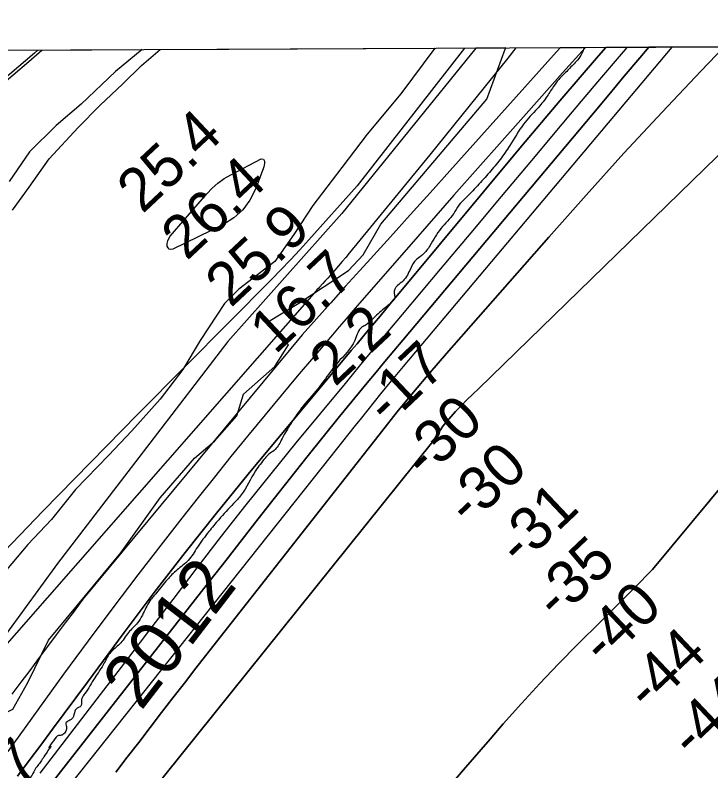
# Model space of a CAD drawing. Extents: x 3424494 to 3462436, y 522220 to 547718.
# Drawn here: x 3448142 to 3449221, y 544764 to 545936 of the extents above; entities that cross this region are included whole.
import ezdxf

# ---------------------------------------------------------------- set-up
doc = ezdxf.new("R2010")
doc.units = 0
for name, color, linetype in [('V-GRID-FRAM', 7, 'Continuous'), ('V-LEVE-TOET', 7, 'Continuous'), ('V-RIVR-EDGE', 7, 'Continuous'), ('V-RIVR-IDEN', 7, 'Continuous'), ('V-RIVR-RANG', 7, 'Continuous'), ('V-SITE-VEGE', 7, 'Continuous'), ('V-TOPO-DPTH', 7, 'Continuous'), ('V-TOPO-MAJR', 7, 'Continuous'), ('V-TOPO-MINR', 7, 'Continuous'), ('V-TOPO-WATR', 7, 'Continuous'), ('V-WETL-SWMP', 7, 'Continuous')]:
    doc.layers.add(name, color=color, linetype=linetype)

msp = doc.modelspace()

# ---------------------------------------------------------------- linework, layer by layer
at = {"layer": 'V-GRID-FRAM'}
for points in [[(3428547.8, 545793.2), (3460200.7, 545935.9)], [(3428547.8, 545793.2), (3451467.1, 545896.5)]]:
    msp.add_lwpolyline(points, dxfattribs=at)
at = {"layer": 'V-LEVE-TOET'}
msp.add_lwpolyline([(3448177, 545881.7), (3448171.9, 545876.8), (3448060.2, 545782.3), (3448035.6, 545758.1), (3448021.3, 545739), (3448005.8, 545710.4), (3447991.9, 545685.8), (3447953.7, 545644.5), (3447873.8, 545571), (3447770.9, 545482), (3447709.3, 545429.6), (3447592.4, 545332.3), (3447519.7, 545267.2), (3447440.2, 545198.9), (3447431.5, 545190.1), (3447416.4, 545175.4), (3447410.4, 545170.3), (3447402.1, 545163.9), (3447381.8, 545146.8), (3447242.3, 545026.9), (3447093.7, 544898.2), (3446965.7, 544788.2), (3446817.5, 544663.1)], dxfattribs=at)
at = {"layer": 'V-RIVR-EDGE'}
msp.add_spline([(3449024.5, 545885.5), (3449019.3, 545873.5), (3449011.8, 545864), (3448999, 545850.5), (3448985, 545836.1), (3448976.3, 545824.5), (3448965.5, 545808.1), (3448951.4, 545790.8), (3448930.4, 545766.9), (3448908.8, 545733.6), (3448893.9, 545712.1), (3448877.4, 545692), (3448858.8, 545671.4), (3448838.9, 545650.8), (3448829.8, 545641), (3448822, 545628.2), (3448802.1, 545605.2), (3448785.1, 545578.4), (3448774, 545564.8), (3448769, 545560.7), (3448761.1, 545553.7), (3448753.7, 545540.1), (3448748.7, 545530.6), (3448741.3, 545522), (3448732.6, 545514.6), (3448730.5, 545510.9), (3448729.7, 545504.3), (3448730.5, 545498.5), (3448726.4, 545491.9), (3448714, 545480.8), (3448695.8, 545464.4), (3448686.3, 545455.7), (3448680.1, 545452.4), (3448668.5, 545431.4), (3448642, 545397.3), (3448623, 545372.2), (3448598.5, 545341.7), (3448586.1, 545326.9), (3448567.5, 545299.7), (3448554.3, 545276.7), (3448543.5, 545261), (3448535.2, 545255.3), (3448529.4, 545249.1), (3448514.6, 545229.3), (3448492.2, 545191.9), (3448480.6, 545178.7), (3448457.5, 545153.6), (3448442.1, 545135.1), (3448424.4, 545110.8), (3448410.3, 545090.6), (3448392.9, 545075.8), (3448377.6, 545060.6), (3448361.1, 545040.4), (3448350.7, 545027.7), (3448339.1, 545005.8), (3448331.3, 544993.5), (3448317.6, 544978.7), (3448303.6, 544960.5), (3448289.9, 544948.2), (3448280, 544931.7), (3448265.1, 544908.3), (3448249.8, 544884), (3448245.2, 544876.6), (3448244.4, 544872.9), (3448244.4, 544867.1), (3448242.3, 544863.4), (3448237.7, 544861.3), (3448234.4, 544856.8), (3448231.1, 544846.5), (3448224.9, 544842), (3448220.4, 544838.3), (3448221.6, 544830.8), (3448219.1, 544824.3), (3448214.5, 544819.7), (3448208.8, 544818.9), (3448205.5, 544816.4), (3448194.7, 544800.4), (3448196.4, 544802), (3448189.7, 544791.3), (3448179.4, 544775.7), (3448174, 544768.7), (3448167.4, 544757.2), (3448157.4, 544744.4), (3448145.4, 544730.8), (3448135.1, 544715.2), (3448124.8, 544701.2), (3448119.4, 544699.9), (3448113.2, 544693), (3448107.4, 544682.7), (3448106.1, 544678.9), (3448100.3, 544665.8), (3448092.9, 544652.2), (3448086.3, 544642.3), (3448078.8, 544638.2), (3448075.5, 544633.2), (3448067.2, 544618.8), (3448046.1, 544585.9), (3448037.4, 544569.4), (3448028.3, 544560.4), (3448024.6, 544560), (3448021.7, 544557.1), (3448012.6, 544541.4), (3448005.1, 544530.7), (3447995.6, 544524.6), (3447994.8, 544522.1), (3447994.4, 544515.5), (3447992.3, 544513.4), (3447987, 544513), (3447986.9, 544505.6), (3447985.7, 544501.9), (3447978.3, 544497.8), (3447969.6, 544490), (3447961.3, 544476.4), (3447954.7, 544466.9), (3447950.1, 544453.7), (3447948, 544444.7), (3447946.4, 544440.1), (3447940.2, 544435.2), (3447932.3, 544427.8), (3447921.6, 544414.6), (3447905.4, 544390.8), (3447884.7, 544360.7), (3447854.9, 544322.4), (3447838, 544301.8), (3447830.9, 544294), (3447828, 544286.2), (3447823.9, 544273.8), (3447817.7, 544265.2), (3447807.7, 544251.6), (3447798.6, 544239.7), (3447792, 544235.1), (3447787.5, 544230.2), (3447785.4, 544227.7), (3447783.7, 544218.3), (3447781.7, 544216.2), (3447776.3, 544210.9), (3447766.4, 544194.8), (3447753.1, 544178.7), (3447722.9, 544136.3), (3447707.6, 544119.1), (3447694.8, 544104.2), (3447681.1, 544084.1), (3447673.7, 544073.8), (3447667, 544060.6), (3447657.1, 544050.3), (3447653.8, 544047.4), (3447652.2, 544044.1), (3447650.1, 544037.5), (3447645.5, 544031.8), (3447640.2, 544026.8), (3447633.1, 544020.3), (3447624.9, 544014.5), (3447616.6, 544013.7), (3447613.3, 544010), (3447605, 544000.9), (3447598.8, 543989), (3447590.1, 543972.9), (3447575.6, 543949.5), (3447562.4, 543928.5), (3447550.8, 543912), (3447539.6, 543898), (3447530.9, 543888.1), (3447527.6, 543882.8), (3447525.5, 543874.1), (3447521.8, 543870.4), (3447516, 543864.7), (3447515.2, 543861), (3447514.8, 543854.8), (3447509.8, 543851.1), (3447503.2, 543848.2), (3447495.3, 543829.7), (3447484.6, 543819), (3447471.8, 543804.1), (3447462.7, 543795.1), (3447454, 543781.9), (3447440.3, 543762.2), (3447430.4, 543746.5), (3447426.2, 543740.3), (3447424.1, 543732.1), (3447421.7, 543729.2), (3447414.2, 543721.8), (3447406, 543717.3), (3447398.5, 543709.9), (3447394, 543701.2), (3447391.1, 543696.3), (3447384, 543692.2), (3447379.5, 543687.7), (3447373.7, 543676.1), (3447366.2, 543663.8), (3447360.4, 543649.4), (3447357.9, 543636.6), (3447352.5, 543628.8), (3447345.1, 543626.7), (3447341.4, 543623), (3447336.4, 543618.5), (3447328.2, 543607.8), (3447317, 543591.3), (3447306.2, 543572.8), (3447293.8, 543548.9), (3447283.4, 543532), (3447267.3, 543508.1), (3447258.6, 543503.6), (3447254.1, 543498.7), (3447252, 543493.7), (3447247.4, 543485.9), (3447242.1, 543476.8), (3447234.2, 543467), (3447228.4, 543461.6), (3447225.1, 543458.3), (3447223.9, 543452.6), (3447222.6, 543443.9), (3447217.6, 543437.3), (3447211, 543429.9), (3447197.4, 543418.4), (3447193.6, 543413), (3447188.7, 543405.6), (3447177.5, 543390.8), (3447165.1, 543376), (3447155.2, 543362), (3447143.6, 543347.6), (3447132.4, 543332), (3447125.4, 543325.4), (3447119.6, 543316.7), (3447107.2, 543302.3), (3447099.3, 543290), (3447082.4, 543268.2), (3447069.5, 543250.5), (3447056.7, 543231.5), (3447044.7, 543214.2), (3447030.6, 543189.1), (3447016.9, 543167.7), (3447008.7, 543152), (3446997.5, 543133.1), (3446988.4, 543122.4), (3446978.9, 543109.6), (3446965.6, 543092.3), (3446951.1, 543073), (3446946.6, 543071.8), (3446942.5, 543067.7), (3446932.1, 543057), (3446914.3, 543030.2)], degree=3, dxfattribs=at)
at = {"layer": 'V-SITE-VEGE'}
for p, q in [((3448337.6, 545857.7), (3448366.6, 545882.5)), ((3448366.6, 545882.5), (3448792.9, 545884.5)), ((3448792.9, 545884.5), (3448740.2, 545813.6)), ((3448308.5, 545829.4), (3448337.6, 545857.7)), ((3448273.1, 545795.6), (3448308.5, 545829.4)), ((3448740.2, 545813.6), (3448687.5, 545751.5)), ((3448239.3, 545761.8), (3448273.1, 545795.6)), ((3448194.4, 545713.1), (3448239.3, 545761.8)), ((3448687.5, 545751.5), (3448648.2, 545699.6)), ((3448163.7, 545669.1), (3448194.4, 545713.1)), ((3448648.2, 545699.6), (3448603.3, 545640.6)), ((3448137.8, 545633.7), (3448163.7, 545669.1)), ((3448603.3, 545640.6), (3448574.2, 545595.8)), ((3448574.2, 545595.8), (3448544.3, 545554.1)), ((3448544.3, 545554.1), (3448488.5, 545510.9)), ((3448488.5, 545510.9), (3448466.5, 545488.9)), ((3448466.5, 545488.9), (3448428.7, 545431.5)), ((3448428.7, 545431.5), (3448401.9, 545386.7)), ((3448401.9, 545386.7), (3448366.5, 545340.3)), ((3448366.5, 545340.3), (3448322.5, 545291.5)), ((3448322.5, 545291.5), (3448286.3, 545253)), ((3448286.3, 545253), (3448235.1, 545200.3)), ((3448235.1, 545200.3), (3448198.2, 545153.9)), ((3448198.2, 545153.9), (3448161.2, 545115.4)), ((3448161.2, 545115.4), (3448128.1, 545076.1))]:
    msp.add_line(p, q, dxfattribs=at)
for points in [[(3448902.8, 545885), (3448856.5, 545884.7), (3448648.2, 545628.3), (3448471.8, 545429.8), (3448207.3, 545085.7), (3448075, 544904.8), (3447942.8, 544737.2)], [(3447998.2, 544719.9), (3448051.3, 544767.3), (3448087.2, 544797.4), (3448105.7, 544843.6), (3448138, 544859.8), (3448161.2, 544901.4), (3448193.3, 544966.8), (3448305.4, 545102.1), (3448366.7, 545187.6), (3448419.9, 545248.9), (3448451.1, 545275.5), (3448485.7, 545314.8), (3448496.1, 545348.4), (3448544.7, 545391.2), (3448565.5, 545424.7), (3448532, 545459.4), (3448581.7, 545489.5), (3448658.9, 545540), (3448681.3, 545564.2), (3448709, 545611.8), (3448873.2, 545805.4), (3448901.6, 545882.9), (3448902.8, 545885)]]:
    msp.add_lwpolyline(points, dxfattribs=at)
at = {"layer": 'V-TOPO-DPTH'}
for p, q in [((3449058.1, 545885.7), (3448987.2, 545885.3)), ((3449124.6, 545886), (3449058.1, 545885.7)), ((3449241.4, 545886.5), (3449124.6, 545886))]:
    msp.add_line(p, q, dxfattribs=at)
for points in [[(3448987.2, 545885.3), (3448981.6, 545879), (3448816.2, 545694.6), (3448785.4, 545660.4), (3448754.6, 545626.3), (3448723.8, 545592.3), (3448693, 545558.2), (3448676.2, 545539.8), (3448653.8, 545514.9), (3448631.4, 545490), (3448609, 545465.1), (3448586.7, 545440), (3448246.9, 545030.3), (3448233, 545012), (3448219.2, 544993.7), (3448205.4, 544975.3), (3448191.8, 544956.8), (3448178.1, 544938.3), (3448164.4, 544919.9), (3448150.6, 544901.5), (3448136.8, 544883.2)], [(3449058.1, 545885.7), (3449046.7, 545872.6), (3448986.7, 545802.8), (3448927.1, 545732.6), (3448868, 545662), (3448734.6, 545501.5), (3448725.7, 545490.8), (3448716.8, 545480), (3448707.8, 545469.3), (3448698.9, 545458.6), (3448689.9, 545447.9), (3448680.9, 545437.2), (3448672, 545426.5), (3448663.1, 545415.8), (3448503.4, 545224.1), (3448453.9, 545163.7), (3448405.2, 545102.7), (3448357.5, 545040.8), (3448310.6, 544978.5), (3448253.7, 544901.5), (3448235.7, 544877.2), (3448217.7, 544852.9), (3448199.7, 544828.6), (3448181.6, 544804.3), (3448163.6, 544780.1), (3448145.5, 544755.8)], [(3448145.5, 544755.8), (3448163.6, 544780.1), (3448181.6, 544804.3), (3448199.7, 544828.6), (3448217.7, 544852.9), (3448235.7, 544877.2), (3448253.7, 544901.5), (3448310.6, 544978.5), (3448357.5, 545040.8), (3448405.2, 545102.7), (3448453.9, 545163.7), (3448503.4, 545224.1), (3448663.1, 545415.8), (3448672, 545426.5), (3448680.9, 545437.2), (3448689.9, 545447.9), (3448698.9, 545458.6), (3448707.8, 545469.3), (3448716.8, 545480), (3448725.7, 545490.8), (3448734.6, 545501.5), (3448868, 545662), (3448927.1, 545732.6), (3448986.7, 545802.8), (3449046.7, 545872.6), (3449058.1, 545885.7)], [(3449124.6, 545886), (3449110.7, 545869.6), (3449086.6, 545841.1), (3449062.6, 545812.5), (3449038.6, 545784), (3448742.9, 545432), (3448729, 545415.4), (3448715.2, 545398.9), (3448701.5, 545382.3), (3448687.8, 545365.6), (3448645, 545313.5), (3448619.4, 545282), (3448593.9, 545250.4), (3448568.7, 545218.6), (3448543.7, 545186.7), (3448518.8, 545154.7), (3448493.9, 545122.7), (3448468.9, 545090.7), (3448443.9, 545058.7), (3448199.3, 544746.2)], [(3448199.3, 544746.2), (3448443.9, 545058.7), (3448468.9, 545090.7), (3448493.9, 545122.7), (3448518.8, 545154.7), (3448543.7, 545186.7), (3448568.7, 545218.6), (3448593.9, 545250.4), (3448619.4, 545282), (3448645, 545313.5), (3448687.8, 545365.6), (3448701.5, 545382.3), (3448715.2, 545398.9), (3448729, 545415.4), (3448742.9, 545432), (3449038.6, 545784), (3449062.6, 545812.5), (3449086.6, 545841.1), (3449110.7, 545869.6), (3449124.6, 545886)], [(3448268.3, 544626.4), (3448789.7, 545274.9), (3448795.6, 545284.2), (3448802.5, 545294.7), (3448805.2, 545298.6), (3448808, 545302.4), (3448811, 545306), (3448814.2, 545309.6), (3448824.9, 545321.1), (3448833.5, 545330.2), (3448842.4, 545339.2), (3448851.4, 545348), (3448860.5, 545356.6), (3449405.7, 545887.2)], [(3448268.3, 544626.4), (3448789.7, 545274.9), (3448795.6, 545284.2), (3448802.5, 545294.7), (3448805.2, 545298.6), (3448808, 545302.4), (3448811, 545306), (3448814.2, 545309.6), (3448824.9, 545321.1), (3448833.5, 545330.2), (3448842.4, 545339.2), (3448851.4, 545348), (3448860.5, 545356.6), (3449405.7, 545887.2)], [(3448298, 544762.3), (3448315.7, 544785.3), (3448333.3, 544808.4), (3448351, 544831.4), (3448368.6, 544854.5), (3448386.4, 544877.4), (3448404.2, 544900.3), (3448422, 544923.2), (3448709.9, 545289.8), (3448734.5, 545320.6), (3448759.5, 545351.2), (3448785, 545381.4), (3448810.9, 545411.3), (3448969.5, 545591.8), (3449027.6, 545657), (3449086.1, 545721.7), (3449145.5, 545785.6), (3449205.5, 545849), (3449241.4, 545886.5)], [(3449241.4, 545886.5), (3449205.5, 545849), (3449145.5, 545785.6), (3449086.1, 545721.7), (3449027.6, 545657), (3448969.5, 545591.8), (3448810.9, 545411.3), (3448785, 545381.4), (3448759.5, 545351.2), (3448734.5, 545320.6), (3448709.9, 545289.8), (3448422, 544923.2), (3448404.2, 544900.3), (3448386.4, 544877.4), (3448368.6, 544854.5), (3448351, 544831.4), (3448333.3, 544808.4), (3448315.7, 544785.3), (3448298, 544762.3)], [(3449608.3, 545651.2), (3449130.1, 545076.2), (3449102.3, 545048.2), (3449074.3, 545020.2), (3449046.3, 544992.3), (3449018.2, 544964.4), (3449014.3, 544960.5), (3448984.6, 544930.4), (3448955.4, 544899.9), (3448926.9, 544868.6), (3448898.9, 544836.9), (3448878.5, 544813.2), (3448840.5, 544769.4), (3448802.4, 544725.6)], [(3448802.4, 544725.6), (3448840.5, 544769.4), (3448878.5, 544813.2), (3448898.9, 544836.9), (3448926.9, 544868.6), (3448955.4, 544899.9), (3448984.6, 544930.4), (3449014.3, 544960.5), (3449018.2, 544964.4), (3449046.3, 544992.3), (3449074.3, 545020.2), (3449102.3, 545048.2), (3449130.1, 545076.2), (3449608.3, 545651.2)]]:
    msp.add_lwpolyline(points, dxfattribs=at)
at = {"layer": 'V-TOPO-MAJR'}
msp.add_lwpolyline([(3448378.4, 545585.9), (3448380, 545589.5), (3448382.3, 545593), (3448438.9, 545658.9), (3448447.2, 545667.6), (3448456.2, 545675.5), (3448465.9, 545682.4), (3448476.3, 545688.5), (3448523.4, 545712.9), (3448527, 545712.8), (3448528.6, 545709.6), (3448528.4, 545706.6), (3448527.9, 545703.5), (3448527.2, 545700.6), (3448526.3, 545697.7), (3448514.5, 545666), (3448505.8, 545649), (3448494.9, 545633.8), (3448480.9, 545621.5), (3448464.8, 545611.1), (3448386.4, 545572.8), (3448383.3, 545572.4), (3448380.8, 545573), (3448378.9, 545574.9), (3448377.6, 545577.7), (3448377.7, 545581.9), (3448378.4, 545585.9)], dxfattribs=at)
at = {"layer": 'V-TOPO-MINR'}
for points in [[(3448838.6, 545884.7), (3448672, 545671), (3448597.4, 545587.7), (3448583.1, 545572), (3448568.7, 545556.4), (3448554, 545541.1), (3448539.2, 545525.9), (3448405.8, 545391.8), (3448332, 545317.3), (3448258.4, 545242.5), (3448185.3, 545167.3), (3448112.4, 545091.9), (3447993.5, 544968.3), (3447980.3, 544954.4), (3447967.4, 544940.5), (3447485.7, 544294.2)], [(3448918.4, 545885), (3448905.8, 545869.2), (3448845.5, 545794.2), (3448784.7, 545719.4), (3448659.8, 545566.8), (3448654.4, 545560.2), (3448648.9, 545553.7), (3448643.3, 545547.2), (3448637.8, 545540.7), (3448634, 545536.4), (3448630.2, 545532.2), (3448626.5, 545528), (3448622.7, 545523.8), (3448618.9, 545519.6), (3448613.8, 545514.2), (3448612.5, 545512.8), (3448609.9, 545510), (3448608.6, 545508.6), (3448051.7, 544873.9), (3448043.1, 544862.1), (3448034.7, 544850.1), (3447859, 544602.8)], [(3449026.3, 545885.5), (3448990.8, 545846.2), (3448934.2, 545783.1), (3448821.9, 545656.5), (3448766.1, 545592.8), (3448676.3, 545489.6), (3448665.6, 545477.3), (3448654.9, 545465), (3448644.3, 545452.6), (3448633.8, 545440.3), (3448604.4, 545405.7), (3448579.3, 545375.9), (3448554.3, 545346), (3448529.4, 545316), (3448504.6, 545286), (3448502.3, 545283.1), (3448476.5, 545251.5), (3448450.9, 545219.7), (3448425.4, 545187.8), (3448400.1, 545155.8), (3448371.2, 545119), (3448331.9, 545068.3), (3448293, 545017.2), (3448254.8, 544965.7), (3448216.9, 544913.9), (3448130.6, 544794)], [(3448987.2, 545885.3), (3448981.6, 545879), (3448816.2, 545694.6), (3448785.4, 545660.4), (3448754.6, 545626.3), (3448723.8, 545592.3), (3448693, 545558.2), (3448676.2, 545539.8), (3448653.8, 545514.9), (3448631.4, 545490), (3448609, 545465.1), (3448586.7, 545440), (3448246.9, 545030.3), (3448233, 545012), (3448219.2, 544993.7), (3448205.4, 544975.3), (3448191.8, 544956.8), (3448178.1, 544938.3), (3448164.4, 544919.9), (3448150.6, 544901.5), (3448136.8, 544883.2)], [(3449090.4, 545885.8), (3449084.7, 545879.1), (3449045.2, 545832.5), (3449005.8, 545785.9), (3448989.9, 545766.9), (3448942.7, 545710.7), (3448895.5, 545654.5), (3448848.3, 545598.2), (3448801.1, 545542), (3448742.2, 545471.8), (3448719.9, 545445.2), (3448697.7, 545418.5), (3448675.5, 545391.8), (3448653.4, 545365), (3448577.1, 545272.7), (3448538.1, 545224.8), (3448499.4, 545176.7), (3448461.3, 545128.1), (3448423.7, 545079.1), (3448386.2, 545030), (3448348.8, 544980.9), (3448311.2, 544931.9), (3448273.7, 544882.8), (3448197, 544782.9), (3448179.9, 544760.4)], [(3449124.6, 545886), (3449110.7, 545869.6), (3449086.6, 545841.1), (3449062.6, 545812.5), (3449038.6, 545784), (3448742.9, 545432), (3448729, 545415.4), (3448715.2, 545398.9), (3448701.5, 545382.3), (3448687.8, 545365.6), (3448645, 545313.5), (3448619.4, 545282), (3448593.9, 545250.4), (3448568.7, 545218.6), (3448543.7, 545186.7), (3448518.8, 545154.7), (3448493.9, 545122.7), (3448468.9, 545090.7), (3448443.9, 545058.7), (3448199.3, 544746.2)], [(3449160.2, 545886.1), (3448743.5, 545391), (3448738.4, 545384.9), (3448733.3, 545378.7), (3448728.2, 545372.5), (3448723.1, 545366.3), (3448708.5, 545348.5), (3448698.6, 545336.3), (3448688.7, 545324), (3448678.8, 545311.7), (3448669, 545299.4), (3448659.3, 545287), (3448649.5, 545274.6), (3448639.7, 545262.3), (3448629.9, 545250), (3448201.2, 544710.5)], [(3449405.7, 545887.2), (3448860.5, 545356.6), (3448851.4, 545348), (3448842.4, 545339.2), (3448833.5, 545330.2), (3448824.9, 545321.1), (3448814.2, 545309.6), (3448811, 545306), (3448808, 545302.4), (3448805.2, 545298.6), (3448802.5, 545294.7), (3448795.6, 545284.2), (3448789.7, 545274.9), (3448268.3, 544626.4)], [(3449241.4, 545886.5), (3449205.5, 545849), (3449145.5, 545785.6), (3449086.1, 545721.7), (3449027.6, 545657), (3448969.5, 545591.8), (3448810.9, 545411.3), (3448785, 545381.4), (3448759.5, 545351.2), (3448734.5, 545320.6), (3448709.9, 545289.8), (3448422, 544923.2), (3448404.2, 544900.3), (3448386.4, 544877.4), (3448368.6, 544854.5), (3448351, 544831.4), (3448333.3, 544808.4), (3448315.7, 544785.3), (3448298, 544762.3)], [(3448802.4, 544725.6), (3448840.5, 544769.4), (3448878.5, 544813.2), (3448898.9, 544836.9), (3448926.9, 544868.6), (3448955.4, 544899.9), (3448984.6, 544930.4), (3449014.3, 544960.5), (3449018.2, 544964.4), (3449046.3, 544992.3), (3449074.3, 545020.2), (3449102.3, 545048.2), (3449130.1, 545076.2), (3449608.3, 545651.2)]]:
    msp.add_lwpolyline(points, dxfattribs=at)
at = {"layer": 'V-TOPO-WATR'}
msp.add_lwpolyline([(3449058.1, 545885.7), (3449046.7, 545872.6), (3448986.7, 545802.8), (3448927.1, 545732.6), (3448868, 545662), (3448734.6, 545501.5), (3448725.7, 545490.8), (3448716.8, 545480), (3448707.8, 545469.3), (3448698.9, 545458.6), (3448689.9, 545447.9), (3448680.9, 545437.2), (3448672, 545426.5), (3448663.1, 545415.8), (3448503.4, 545224.1), (3448453.9, 545163.7), (3448405.2, 545102.7), (3448357.5, 545040.8), (3448310.6, 544978.5), (3448253.7, 544901.5), (3448235.7, 544877.2), (3448217.7, 544852.9), (3448199.7, 544828.6), (3448181.6, 544804.3), (3448163.6, 544780.1), (3448145.5, 544755.8)], dxfattribs=at)
at = {"layer": 'V-WETL-SWMP'}
for p, q in [((3448163, 545864.1), (3448183.1, 545881.7)), ((3448183.1, 545881.7), (3448338.8, 545882.4)), ((3448338.8, 545882.4), (3448297.5, 545848.3)), ((3448075.7, 545790.2), (3448163, 545864.1)), ((3448297.5, 545848.3), (3448244, 545798)), ((3448244, 545798), (3448205.5, 545765)), ((3448205.5, 545765), (3448163.8, 545724.1)), ((3448163.8, 545724.1), (3448132.3, 545677.7))]:
    msp.add_line(p, q, dxfattribs=at)

# ---------------------------------------------------------------- texts
at = {"layer": 'V-RIVR-IDEN'}
msp.add_text(' 2012', height=83, rotation=52.4252, dxfattribs=at).set_placement((3448318.2, 544831.5))
at = {"layer": 'V-RIVR-RANG'}
for s, rotation, p in [('25.4', 43.1783, (3448339.2, 545626.8)), ('26.4', 43.1783, (3448407.8, 545554)), ('25.9', 43.1783, (3448476.2, 545481.1)), ('16.7', 43.1783, (3448545, 545408.5)), ('2.2', 43.1783, (3448637.8, 545358.5)), ('-17', 43.457, (3448720, 545298)), ('-30', 43.457, (3448777.3, 545214.6)), ('-30', 43.457, (3448845.9, 545141.8)), ('-31', 43.457, (3448925.2, 545079.2)), ('-35', 43.457, (3448982.5, 544995.8)), ('-40', 43.457, (3449054.4, 544926.1)), ('-44', 43.457, (3449123.8, 544854.1)), ('-44', 43.457, (3449192.4, 544781.3)), ('4.7', 43.8383, (3448094, 544686))]:
    msp.add_text(s, height=67, rotation=rotation, dxfattribs=at).set_placement(p)

doc.saveas('drawing.dxf')
